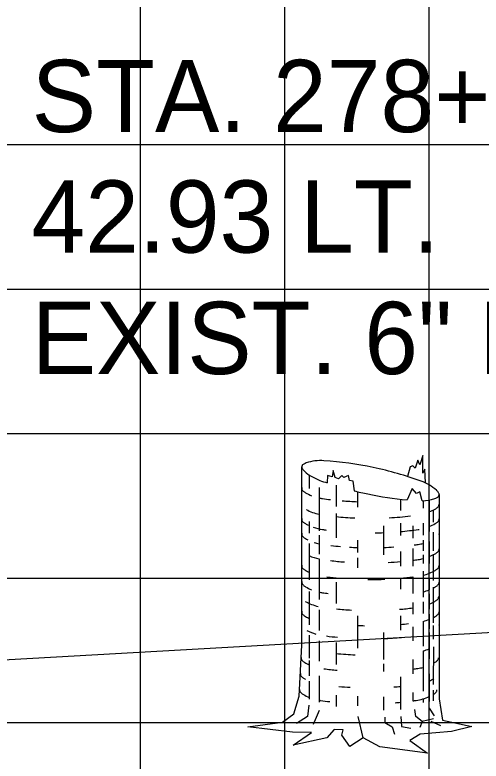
# Model space of a CAD drawing. Extents: x 854676 to 854846, y 366268 to 366378.
# Drawn here: x 854713.24 to 854716.47, y 366308.97 to 366314.13 of the extents above; entities that cross this region are included whole.
import ezdxf

# ---------------------------------------------------------------- set-up
doc = ezdxf.new("R2010")
doc.units = 0
for name, color, linetype in [('D_Text_Monospaced', 7, 'Continuous'), ('MAJOR', 7, 'Continuous'), ('MINOR', 7, 'Continuous'), ('S_Roadway_Centerline', 7, 'Continuous'), ('S_Trees_Decid_NonPay', 7, 'Continuous')]:
    doc.layers.add(name, color=color, linetype=linetype)

msp = doc.modelspace()

# ---------------------------------------------------------------- linework, layer by layer
at = {"layer": 'MAJOR'}
for p, q in [((854714.1063, 366302.2365), (854714.1063, 366317.2365)), ((854689.1063, 366312.2365), (854829.1063, 366312.2365))]:
    msp.add_line(p, q, dxfattribs=at)
at = {"layer": 'MINOR'}
for p, q in [((854715.1063, 366302.2365), (854715.1063, 366317.2365)), ((854716.1063, 366302.2365), (854716.1063, 366317.2365)), ((854689.1063, 366313.2365), (854829.1063, 366313.2365)), ((854689.1063, 366311.2365), (854829.1063, 366311.2365)), ((854689.1063, 366310.2365), (854829.1063, 366310.2365)), ((854689.1063, 366309.2365), (854829.1063, 366309.2365))]:
    msp.add_line(p, q, dxfattribs=at)
at = {"layer": 'S_Roadway_Centerline'}
msp.add_lwpolyline([(854702.4781, 366309.0686), (854721.1334, 366310.1212), (854725.4486, 366310.2115), (854732.9397, 366310.7459), (854735.5449, 366310.3698), (854737.3151, 366310.5471), (854738.2609, 366310.5131), (854740.7883, 366310.3627), (854741.6634, 366310.0477), (854741.9478, 366309.9565), (854743.8837, 366310.0246), (854748.4288, 366310.2045), (854751.4741, 366310.1688), (854759.5515, 366310.1685), (854768.432, 366309.9647), (854771.5262, 366309.8917)], dxfattribs=at)
at = {"layer": 'S_Trees_Decid_NonPay'}
for p, q in [((854715.2754, 366310.9499), (854715.2754, 366310.8554)), ((854715.3437, 366310.8633), (854715.3437, 366310.5628)), ((854715.4624, 366310.8804), (854715.4624, 366310.7321)), ((854715.6094, 366310.8344), (854715.6094, 366310.7275)), ((854715.9067, 366310.7819), (854715.9067, 366310.7032)), ((854716.0641, 366310.7714), (854716.0641, 366310.7196)), ((854716.1068, 366310.7767), (854716.1068, 366310.5589)), ((854716.1337, 366310.7065), (854716.1337, 366310.6245)), ((854715.4624, 366310.6842), (854715.4624, 366310.5155)), ((854715.2754, 366310.6291), (854715.2754, 366310.5464)), ((854715.9067, 366310.6166), (854715.9067, 366310.5319)), ((854716.0641, 366310.6166), (854716.0641, 366310.5339)), ((854715.7892, 366310.5982), (854715.7892, 366310.3981)), ((854715.9933, 366310.5982), (854715.9933, 366310.5116)), ((854716.1337, 366310.5549), (854716.1337, 366310.425)), ((854715.3437, 366310.5339), (854715.3437, 366310.4027)), ((854715.6094, 366310.4991), (854715.6094, 366310.4125)), ((854716.0641, 366310.4991), (854716.0641, 366310.425)), ((854715.2754, 366310.4768), (854715.2754, 366310.2255)), ((854716.1068, 366310.49), (854716.1068, 366310.3384)), ((854715.9067, 366310.4211), (854715.9067, 366310.32)), ((854715.9933, 366310.4414), (854715.9933, 366310.32)), ((854716.0641, 366310.3981), (854716.0641, 366310.3384)), ((854716.1337, 366310.4027), (854716.1337, 366310.2209)), ((854715.3437, 366310.3686), (854715.3437, 366310.0877)), ((854715.6094, 366310.3777), (854715.6094, 366310.3075)), ((854715.9933, 366310.2445), (854715.9933, 366310.1304)), ((854716.0641, 366310.2852), (854716.0641, 366310.1041)), ((854715.4624, 366310.2091), (854715.4624, 366310.0608)), ((854715.9067, 366310.2354), (854715.9067, 366310.1592)), ((854716.1068, 366310.2334), (854716.1068, 366310.1553)), ((854715.2754, 366310.1428), (854715.2754, 366309.9125)), ((854716.1337, 366310.1737), (854716.1337, 366309.927)), ((854716.1068, 366310.1284), (854716.1068, 366310.0214)), ((854715.9933, 366310.0687), (854715.9933, 366309.9867)), ((854716.0641, 366310.0726), (854716.0641, 366309.9906)), ((854715.3437, 366310.0175), (854715.3437, 366309.8732)), ((854716.1068, 366309.9867), (854716.1068, 366309.8856)), ((854715.6094, 366309.9742), (854715.6094, 366309.7518)), ((854715.9067, 366309.9742), (854715.9067, 366309.8771)), ((854716.0641, 366309.9368), (854716.0641, 366309.7662)), ((854715.9933, 366309.9001), (854715.9933, 366309.8029)), ((854716.1337, 366309.9079), (854716.1337, 366309.8134)), ((854715.2754, 366309.8423), (854715.2754, 366309.6816)), ((854715.7892, 366309.8607), (854715.7892, 366309.6737)), ((854716.1068, 366309.86), (854716.1068, 366309.6776)), ((854715.3437, 366309.8029), (854715.3437, 366309.6612)), ((854715.4624, 366309.7911), (854715.4624, 366309.6382)), ((854716.0641, 366309.7327), (854716.0641, 366309.4532)), ((854716.1357, 366309.7603), (854716.1343, 366309.5005)), ((854715.9933, 366309.6737), (854715.9933, 366309.5746)), ((854715.2754, 366309.6652), (854715.2754, 366309.5602)), ((854715.7892, 366309.6428), (854715.7892, 366309.5897)), ((854716.1068, 366309.5746), (854716.1068, 366309.383)), ((854715.2754, 366309.5234), (854715.2754, 366309.3994)), ((854715.3437, 366309.5602), (854715.3437, 366309.3791)), ((854715.9067, 366309.5523), (854715.9067, 366309.3279)), ((854715.4624, 366309.4263), (854715.4624, 366309.3482)), ((854715.6094, 366309.4184), (854715.6094, 366309.3522)), ((854715.7892, 366309.4138), (854715.7892, 366309.3233)), ((854715.9933, 366309.4453), (854715.9933, 366309.3869)), ((854716.1337, 366309.4617), (854716.1337, 366309.3876)), ((854716.0641, 366309.4007), (854716.0641, 366309.3751)), ((854715.343, 366309.3194), (854715.3017, 366309.2229)), ((854716.1048, 366309.3358), (854716.1396, 366309.2846)), ((854715.6494, 366309.1323), (854715.6147, 366309.278)), ((854716.1868, 366309.2144), (854716.1193, 366309.2452))]:
    msp.add_line(p, q, dxfattribs=at)
for points in [[(854716.0799, 366310.8948), (854716.0759, 366310.9893), (854716.0615, 366310.9624), (854716.0615, 366311.0838), (854716.0405, 366311.0201), (854716.0261, 366311.0529), (854716.0097, 366310.9972), (854715.9933, 366311.0142), (854715.9749, 366311.0057), (854715.9559, 366310.9388)], [(854716.175, 366310.8141), (854716.175, 366309.402), (854716.1973, 366309.2537), (854716.4007, 366309.2104), (854716.261, 366309.175), (854716.0425, 366309.1566), (854715.9729, 366309.1133), (854716.0943, 366309.0247), (854715.763, 366309.068), (854715.6494, 366309.1323), (854715.5569, 366309.072), (854715.5011, 366309.1507), (854715.5097, 366309.1875), (854715.448, 366309.1894), (854715.3962, 366309.1323), (854715.1639, 366309.0805), (854715.2912, 366309.1691), (854715.1593, 366309.1711), (854714.8509, 366309.2085), (854715.0897, 366309.2393), (854715.1678, 366309.297), (854715.2065, 366309.4184), (854715.2236, 366309.7721), (854715.2236, 366311.0057)], [(854715.5878, 366310.8397), (854715.5792, 366310.9066), (854715.5549, 366310.9112), (854715.5464, 366310.946), (854715.5156, 366310.9316), (854715.5011, 366310.946), (854715.4769, 366310.923), (854715.4539, 366310.9316), (854715.4414, 366310.9808), (854715.4336, 366310.9375), (854715.4027, 366310.946), (854715.3994, 366310.8948)], [(854716.0576, 366310.7708), (854716.0405, 366310.8325), (854716.0182, 366310.8207), (854715.9874, 366310.8554), (854715.9539, 366310.7774)], [(854715.2728, 366309.3568), (854715.2643, 366309.28), (854715.1862, 366309.2308)], [(854716.0569, 366309.2452), (854716.0136, 366309.28), (854716.0057, 366309.3279)], [(854715.7977, 366309.2741), (854715.7977, 366309.2373), (854715.8489, 366309.2065), (854715.866, 366309.1566)], [(854715.9093, 366309.28), (854715.9152, 366309.2104), (854715.9788, 366309.198)], [(854716.1357, 366309.2616), (854716.0569, 366309.2452), (854716.0405, 366309.2019)]]:
    msp.add_lwpolyline(points, dxfattribs=at)
for centre, radius, start, end in [((854715.2418, 366311.0058), 0.0179, 152.1168, 168.1723), ((854715.2469, 366311.0031), 0.0237, 138.1723, 152.1168), ((854715.2543, 366310.9965), 0.0336, 119.396, 138.1723), ((854715.2837, 366310.9443), 0.0935, 108.1723, 119.396), ((854715.3549, 366310.7273), 0.3218, 86.0543, 108.1723), ((854715.2045, 366308.5474), 2.507, 78.1723, 86.0543), ((854715.2418, 366311.0058), 0.0179, 168.1723, 184.2278), ((854715.2476, 366311.0062), 0.0237, 184.2278, 198.1723), ((854715.257, 366311.0093), 0.0336, 198.1723, 216.9486), ((854715.3048, 366311.0453), 0.0935, 216.9486, 228.1723), ((854715.4571, 366311.2154), 0.3218, 228.1723, 250.2902), ((854715.2045, 366308.5474), 2.507, 70.2902, 78.1723), ((854716.194, 366313.2725), 2.507, 250.2902, 251.5281), ((854715.2422, 366310.8584), 0.0191, 163.9485, 180), ((854715.2422, 366310.8584), 0.0191, 180, 196.0515), ((854715.9415, 366310.6045), 0.3218, 48.1723, 70.2902), ((854715.2481, 366310.8601), 0.0252, 196.0515, 210), ((854715.2571, 366310.8653), 0.0356, 210, 228.7494), ((854715.2985, 366310.9125), 0.0984, 228.7494, 240), ((854715.4124, 366311.1097), 0.3261, 240, 248.3243), ((854716.194, 366313.2725), 2.507, 255.9987, 258.1723), ((854716.194, 366313.2725), 2.507, 258.1723, 264.5013), ((854716.0938, 366310.7746), 0.0935, 36.9486, 48.1723), ((854716.1416, 366310.8106), 0.0336, 18.1723, 36.9486), ((854716.1568, 366310.8142), 0.0179, 332.1168, 348.1723), ((854716.151, 366310.8137), 0.0237, 4.2278, 18.1723), ((854716.1568, 366310.8142), 0.0179, 348.1723, 4.2278), ((854715.4124, 366311.1097), 0.3261, 257.8036, 261.8968), ((854715.6985, 366313.1197), 2.3564, 261.8968, 263.2799), ((854715.6985, 366313.1197), 2.3564, 265.24, 267.8386), ((854716.0437, 366311.0926), 0.3218, 272.4479, 288.1723), ((854716.1149, 366310.8756), 0.0935, 288.1723, 299.396), ((854716.1443, 366310.8235), 0.0336, 299.396, 318.1723), ((854716.1517, 366310.8169), 0.0237, 318.1723, 332.1168), ((854715.4124, 366310.9964), 0.3261, 240.9099, 257.8036), ((854715.9847, 366310.9964), 0.3261, 291.9506, 300), ((854716.0986, 366310.7992), 0.0984, 300, 311.2506), ((854716.14, 366310.752), 0.0356, 311.2506, 330), ((854716.149, 366310.7468), 0.0252, 330, 343.9485), ((854716.1549, 366310.7451), 0.0191, 343.9485, 360), ((854716.1549, 366310.7451), 0.0191, 360, 6.1128), ((854715.6985, 366313.0064), 2.3564, 264.242, 267.3673), ((854715.6985, 366313.0064), 2.3564, 273.1481, 276.7734), ((854715.2422, 366310.6442), 0.0191, 163.9485, 180), ((854715.2422, 366310.6442), 0.0191, 180, 196.0515), ((854715.2481, 366310.6459), 0.0252, 196.0515, 210), ((854715.2571, 366310.6511), 0.0356, 210, 228.7494), ((854715.2985, 366310.6984), 0.0984, 228.7494, 240), ((854715.4124, 366310.8955), 0.3261, 240, 243.5719), ((854715.9847, 366310.8955), 0.3261, 291.9506, 300), ((854716.0986, 366310.6984), 0.0984, 300, 311.2506), ((854716.14, 366310.6511), 0.0356, 311.2506, 330), ((854716.149, 366310.6459), 0.0252, 330, 343.9485), ((854716.1549, 366310.6442), 0.0191, 343.9485, 360), ((854716.1549, 366310.6442), 0.0191, 360, 6.1128), ((854715.4124, 366310.8955), 0.3261, 250.4167, 261.8968), ((854715.6985, 366312.9056), 2.3564, 261.8968, 262.5519), ((854715.6985, 366312.9056), 2.3564, 270.8119, 272.1981), ((854715.6985, 366312.9056), 2.3564, 275.0647, 278.1032), ((854715.9847, 366310.8955), 0.3261, 278.1032, 279.0854), ((854715.2422, 366310.5413), 0.0191, 163.9485, 180), ((854715.2422, 366310.5413), 0.0191, 180, 196.0515), ((854715.2481, 366310.543), 0.0252, 196.0515, 210), ((854715.2571, 366310.5482), 0.0356, 210, 228.7494), ((854715.2985, 366310.5954), 0.0984, 228.7494, 240), ((854715.4124, 366310.7926), 0.3261, 240, 243.243), ((854716.1549, 366310.5413), 0.0191, 343.9485, 360), ((854716.1549, 366310.5413), 0.0191, 360, 6.1128), ((854715.4124, 366310.7926), 0.3261, 251.6831, 257.8036), ((854715.6985, 366312.8026), 2.3564, 263.3413, 264.9946), ((854715.6985, 366312.8026), 2.3564, 266.5036, 267.8386), ((854715.6985, 366312.8026), 2.3564, 272.1981, 273.9741), ((854715.6985, 366312.8026), 2.3564, 277.3838, 278.1032), ((854715.9847, 366310.7926), 0.3261, 278.1032, 284.0382), ((854715.9847, 366310.6876), 0.3261, 291.9506, 300), ((854716.0986, 366310.4904), 0.0984, 300, 311.2506), ((854716.14, 366310.4432), 0.0356, 311.2506, 330), ((854716.149, 366310.438), 0.0252, 330, 343.9485), ((854716.1549, 366310.4363), 0.0191, 343.9485, 360), ((854716.1549, 366310.4363), 0.0191, 360, 6.1128), ((854715.4124, 366310.6876), 0.3261, 245.1545, 257.8036), ((854715.6985, 366312.6976), 2.3564, 263.2682, 265.6362), ((854715.6985, 366312.6976), 2.3564, 273.0067, 275.0647), ((854715.6985, 366312.6976), 2.3564, 277.1868, 278.1032), ((854715.9847, 366310.6876), 0.3261, 278.1032, 284.0382), ((854715.2422, 366310.3212), 0.0191, 163.9485, 180), ((854715.2422, 366310.3212), 0.0191, 180, 196.0515), ((854715.2481, 366310.3229), 0.0252, 196.0515, 210), ((854715.2571, 366310.3281), 0.0356, 210, 228.7494), ((854715.2985, 366310.3753), 0.0984, 228.7494, 240), ((854715.4124, 366310.5725), 0.3261, 240, 245.1545), ((854715.9847, 366310.5725), 0.3261, 284.0382, 300), ((854716.0986, 366310.3753), 0.0984, 300, 311.2506), ((854716.14, 366310.3281), 0.0356, 311.2506, 330), ((854716.149, 366310.3229), 0.0252, 330, 343.9485), ((854716.1549, 366310.3212), 0.0191, 343.9485, 360), ((854716.1549, 366310.3212), 0.0191, 360, 6.1128), ((854715.6985, 366312.5826), 2.3564, 262.6588, 264.7911), ((854715.6985, 366312.5826), 2.3564, 275.0647, 277.1868), ((854715.2429, 366310.2068), 0.0191, 163.9485, 180), ((854715.2429, 366310.2068), 0.0191, 180, 196.0515), ((854715.2488, 366310.2085), 0.0252, 196.0515, 210), ((854715.2579, 366310.2137), 0.0356, 210, 228.7494), ((854715.2993, 366310.2609), 0.0984, 228.7494, 240), ((854715.6985, 366312.5826), 2.3564, 269.5578, 270), ((854715.6985, 366312.5826), 2.3564, 270, 272.414), ((854716.0993, 366310.2609), 0.0984, 300, 311.2506), ((854716.1407, 366310.2137), 0.0356, 311.2506, 330), ((854716.1498, 366310.2085), 0.0252, 330, 343.9485), ((854716.1557, 366310.2068), 0.0191, 343.9485, 360), ((854716.1557, 366310.2068), 0.0191, 0, 6.1128), ((854715.4131, 366310.4581), 0.3261, 240, 247.8656), ((854715.4131, 366310.4581), 0.3261, 257.6699, 261.8968), ((854715.6993, 366312.4682), 2.3564, 261.8968, 262.8615), ((854715.9855, 366310.4581), 0.3261, 283.9036, 291.8098), ((854715.9855, 366310.4581), 0.3261, 297.0058, 300), ((854715.2398, 366310.1065), 0.0191, 163.9485, 180), ((854716.0962, 366310.1607), 0.0984, 300, 311.2506), ((854716.1376, 366310.1135), 0.0356, 311.2506, 330), ((854716.1466, 366310.1082), 0.0252, 330, 343.9485), ((854716.1525, 366310.1065), 0.0191, 343.9485, 360), ((854716.1525, 366310.1065), 0.0191, 0, 6.1128), ((854715.41, 366310.3578), 0.3261, 240, 256.9079), ((854715.9823, 366310.3578), 0.3261, 292.4049, 300), ((854715.2422, 366310.0018), 0.0191, 163.9485, 180), ((854715.2422, 366310.0018), 0.0191, 180, 196.0515), ((854715.2481, 366310.0035), 0.0252, 196.0515, 210), ((854715.2571, 366310.0087), 0.0356, 210, 228.7494), ((854715.2985, 366310.056), 0.0984, 228.7494, 240), ((854715.6962, 366312.3679), 2.3564, 264.3443, 266.8529), ((854715.6962, 366312.3679), 2.3564, 274.9734, 277.2455), ((854716.0986, 366310.056), 0.0984, 300, 311.2506), ((854716.14, 366310.0087), 0.0356, 311.2506, 330), ((854716.149, 366310.0035), 0.0252, 330, 343.9485), ((854716.1549, 366310.0018), 0.0191, 343.9485, 360), ((854716.1549, 366310.0018), 0.0191, 360, 6.1128), ((854715.4124, 366310.2531), 0.3261, 240, 245.1545), ((854715.9847, 366310.2531), 0.3261, 284.0382, 291.9506), ((854715.9847, 366310.2531), 0.3261, 297.1525, 300), ((854715.6985, 366312.2632), 2.3564, 267.8386, 269.0054), ((854715.6985, 366312.2632), 2.3564, 275.0647, 276.428), ((854716.1549, 366309.9112), 0.0191, 360, 6.1128), ((854715.4124, 366310.1625), 0.3261, 241.939, 253.9183), ((854715.6985, 366312.1726), 2.3564, 262.5843, 264.4865), ((854715.6985, 366312.1726), 2.3564, 272.1981, 275.2726), ((854715.9847, 366310.0493), 0.3261, 284.0382, 291.9506), ((854715.2381, 366309.6828), 0.0191, 163.9485, 180), ((854715.2381, 366309.6828), 0.0191, 180, 196.0515), ((854715.244, 366309.6845), 0.0252, 196.0515, 210), ((854715.2531, 366309.6897), 0.0356, 210, 228.7494), ((854715.6985, 366312.0593), 2.3564, 264.242, 267.469), ((854716.1359, 366309.6897), 0.0356, 311.2506, 330), ((854716.145, 366309.6845), 0.0252, 330, 343.9485), ((854716.1509, 366309.6828), 0.0191, 343.9485, 360), ((854716.1509, 366309.6828), 0.0191, 360, 6.1128), ((854715.2945, 366309.7369), 0.0984, 228.7494, 240), ((854715.4083, 366309.9341), 0.3261, 240, 245.9375), ((854716.0945, 366309.7369), 0.0984, 300, 311.2506), ((854715.2332, 366309.5722), 0.0191, 163.9485, 180), ((854715.2332, 366309.5722), 0.0191, 180, 196.0515), ((854715.6945, 366311.9441), 2.3564, 262.2226, 264.4852), ((854715.6945, 366311.9441), 2.3564, 277.2863, 278.1032), ((854715.9807, 366309.9341), 0.3261, 278.1032, 284.7741), ((854715.2391, 366309.5739), 0.0252, 196.0515, 210), ((854715.2482, 366309.5791), 0.0356, 210, 228.7494), ((854715.2896, 366309.6263), 0.0984, 228.7494, 240), ((854715.4034, 366309.8235), 0.3261, 240, 241.9097), ((854715.9758, 366309.8235), 0.3261, 293.6544, 300), ((854715.2278, 366309.4619), 0.0191, 163.9485, 180), ((854715.6896, 366311.8335), 2.3564, 264.9089, 266.8158), ((854715.6896, 366311.8335), 2.3564, 274.1864, 275.2829), ((854716.1405, 366309.4619), 0.0191, 0, 6.1128), ((854715.2278, 366309.4619), 0.0191, 180, 196.0515), ((854715.2337, 366309.4636), 0.0252, 196.0515, 210), ((854715.2427, 366309.4688), 0.0356, 210, 228.7494), ((854715.2841, 366309.516), 0.0984, 228.7494, 240), ((854715.3979, 366309.7132), 0.3261, 240, 247.9161), ((854715.9703, 366309.7132), 0.3261, 278.1032, 294.7094), ((854716.0842, 366309.516), 0.0984, 300, 311.2506), ((854716.1256, 366309.4688), 0.0356, 311.2506, 330), ((854716.1346, 366309.4636), 0.0252, 330, 343.9485), ((854716.1405, 366309.4619), 0.0191, 343.9485, 360), ((854715.3979, 366309.7132), 0.3261, 260.3834, 261.8968), ((854715.6841, 366311.7232), 2.3564, 261.8968, 263.5333), ((854715.6841, 366311.7232), 2.3564, 274.5551, 275.4167), ((854715.6841, 366311.7232), 2.3564, 277.5403, 278.1032)]:
    msp.add_arc(centre, radius, start, end, dxfattribs=at)

# ---------------------------------------------------------------- texts
at = {"layer": 'D_Text_Monospaced'}
for s, p in [('STA. 278+56.80', (854713.3529, 366313.3219)), ('42.93 LT.', (854713.3529, 366312.4879)), ('EXIST. 6" MAPLE', (854713.3529, 366311.6479))]:
    msp.add_text(s, height=0.49998, dxfattribs=at).set_placement(p)

doc.saveas('drawing.dxf')
